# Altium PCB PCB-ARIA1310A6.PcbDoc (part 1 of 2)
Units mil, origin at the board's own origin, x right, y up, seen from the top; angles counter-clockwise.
Board outline 6000 x 4000 mil, 2 copper layers (Top Layer, Bottom Layer); 128 components, 134 nets, 554 pads, 227 vias.
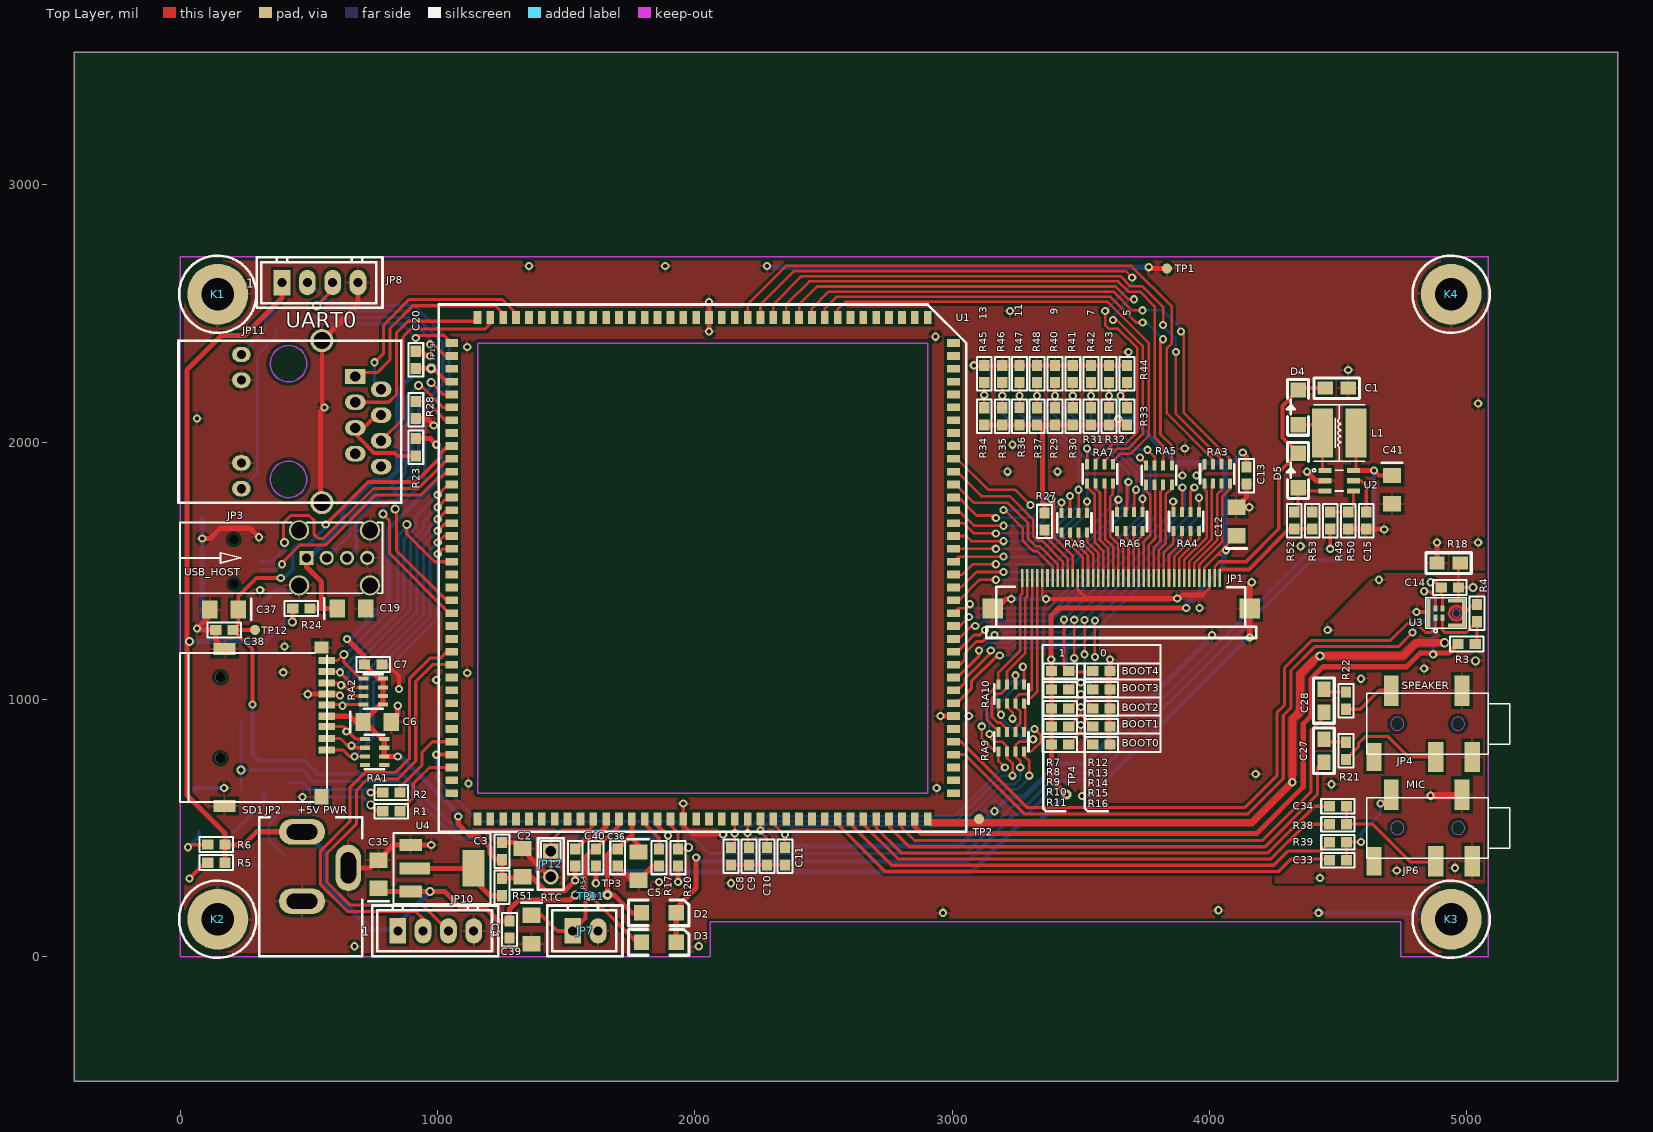
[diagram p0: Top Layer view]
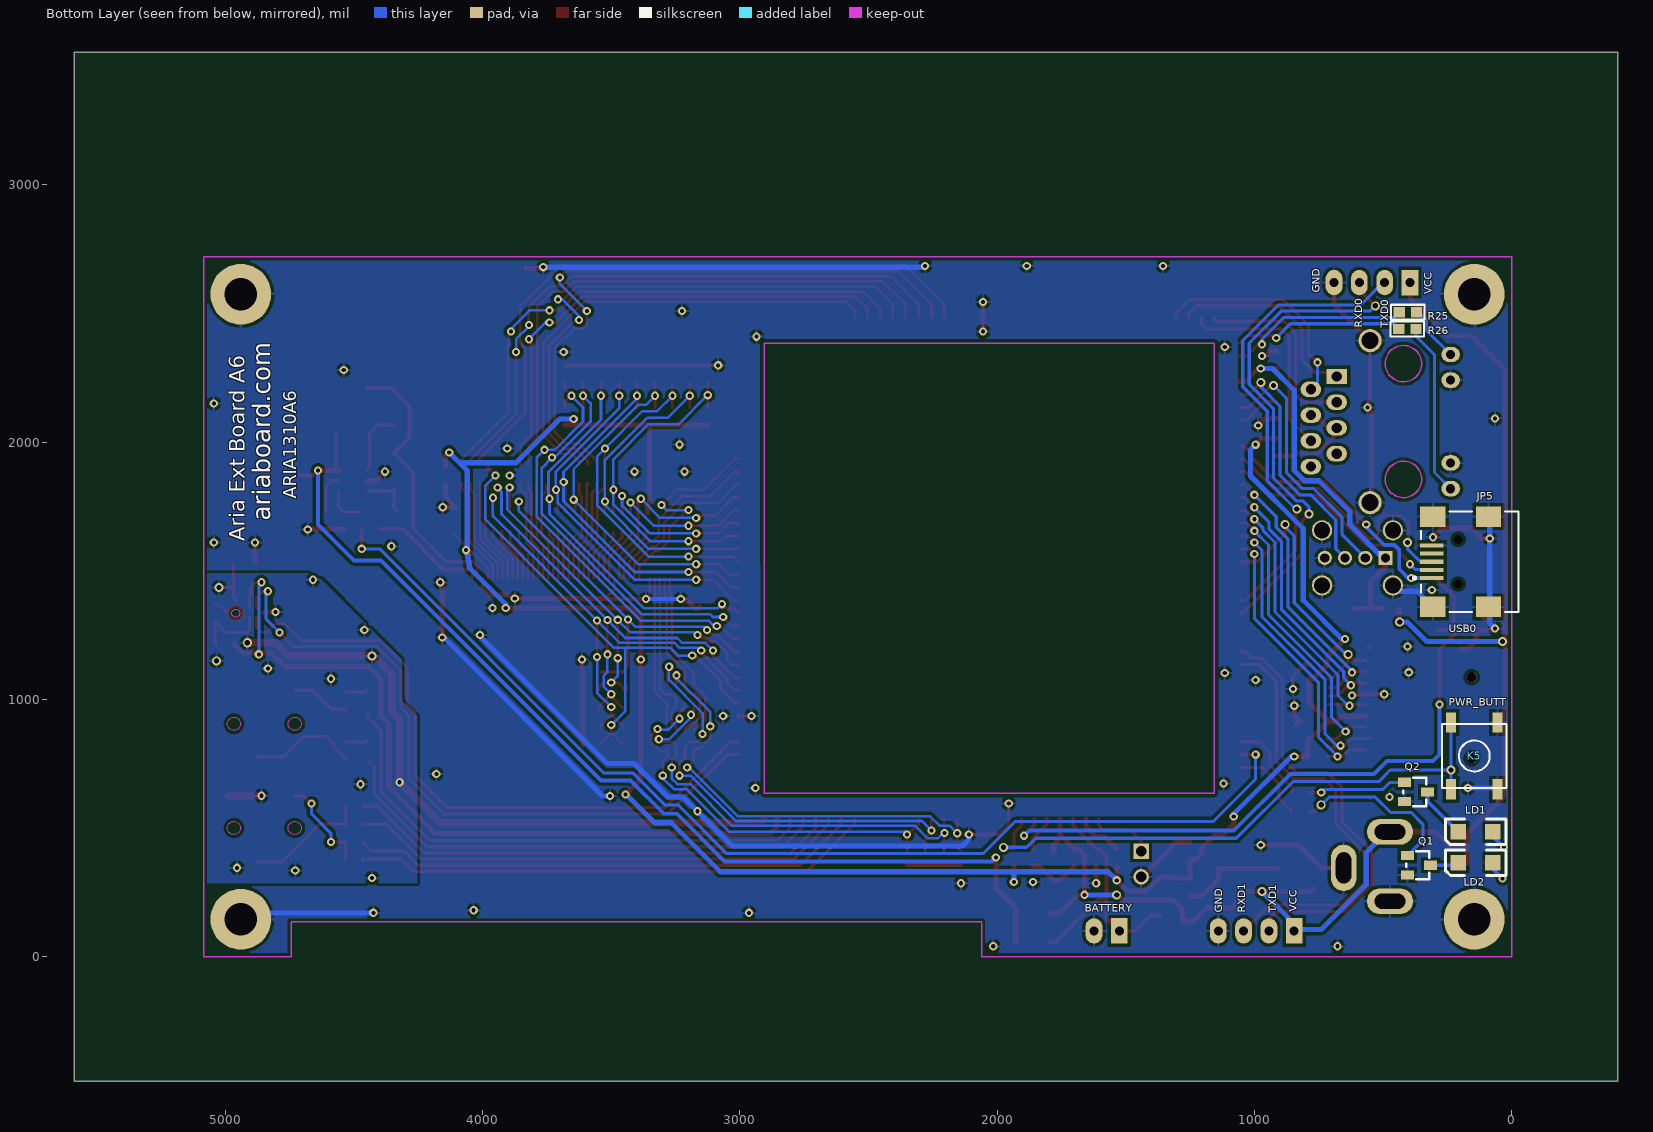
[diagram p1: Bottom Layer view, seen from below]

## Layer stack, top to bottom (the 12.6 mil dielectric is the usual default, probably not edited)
Top Layer: signal copper 1.4
Dielectric: dielectric 12.6, FR-4, Dk 4.8
Bottom Layer: signal copper 1.4

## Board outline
-412.52,-484.61 5587.48,-484.61 5587.48,3515.39 -412.52,3515.39

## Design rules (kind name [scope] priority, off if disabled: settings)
Clearance Clearance_2 [All] p1 off: gap=12
Clearance Clearance_1 [All] p2: gap=8
ComponentClearance [All] p1: gap=0 collisioncheckmode=3 verticalgap=0 showdistances=FALSE
HoleSize [All] p1: absolutevalues=TRUE maxlimit=1000 minlimit=10 maxpercent=80.000 minpercent=20.000
PolygonConnect [All] p1: connectstyle=Relief reliefconductorwidth=10 reliefentries=4 polygonreliefangle="90 Angle"
RoutingVias [All] p1: holewidth=18 width=36 viastyle="Through Hole" minholewidth=12 minwidth=24 maxholewidth=1000 maxwidth=3000
SolderMaskExpansion [All] p1: expansion=4
TestPointUsage FabricationTestPointUsage [All] p1: valid=0 allowmultiple=FALSE
Testpoint FabricationTestpoint [All] p1: side=3 testpointundercomponent=TRUE minsize=40 maxsize=100 preferedsize=60 minholesize=0 maxholesize=40 preferedholesize=32 testpointgrid=1 style=297 order=0123456789
Width Width_2 [InNet('VCC')] p1: maxlimit=50 minlimit=20 preferedwidth=30
Width Width_1 [All] p2: maxlimit=50 minlimit=10 preferedwidth=10
Width [All] p3 off: maxlimit=15 minlimit=12 preferedwidth=12
17 further rules are at their usual default settings.

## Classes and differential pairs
component class LCD: C1 C2 C3 C12 C13 C15 C41 D2 D3 D4 D5 JP1 L1 R27 R49 R50 R52 R53 RA3 RA4 RA5 RA6 RA7 RA8 RA9 RA10 U2
component class Audio&Net: C14 C27 C28 C33 C34 JP4 JP6 JP11 K1 K2 K3 K4 R3 R4 R18 R21 R22 R23 R25 R26 R38 R39 U3
component class Connect: C19 C20 C35 C36 C37 C38 C39 C40 JP2 JP3 JP5 JP7 JP8 JP10 R24 R28 R51 TP1 TP3 TP4 TP11 TP12 TP13 U4
net class LCD_DATA[23..0]: LCD_DATA0 LCD_DATA1 LCD_DATA2 LCD_DATA3 LCD_DATA4 LCD_DATA5 LCD_DATA6 LCD_DATA7 LCD_DATA8 LCD_DATA9 LCD_DATA10 LCD_DATA11 LCD_DATA12 LCD_DATA13 LCD_DATA14 LCD_DATA15 LCD_DATA16 LCD_DATA17 LCD_DATA18 LCD_DATA19 LCD_DATA20 LCD_DATA21 LCD_DATA22 LCD_DATA23
component class Core: C4 C5 C6 C7 C8 C9 C10 C11 JP12 K5 LD1 LD2 Q1 Q2 R1 R2 R5 R6 R7 R8 R9 R10 R11 R12 R13 R14 R15 R16 R17 R20 R29 R30 R31 R32 R33 R34 R35 R36 R37 R40 R41 R42 R43 R44 R45 R46 R47 R48 R54 RA1 RA2 SD1 TP2 U1

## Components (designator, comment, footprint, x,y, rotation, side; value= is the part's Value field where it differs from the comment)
C1 "1uF" U2012-0805 4495,2210 r0 top
C2 "10uF" CC3216-1206#1 1330,365 r90 top
C3 "100nF" U1608-0603 1250,410 r270 top
C4 "100nF" U1608-0603 1280,105 r90 top
C5 "10uF" CC3216-1206#1 1780,351.54 r270 top
C6 "10uF" CC3216-1206#1 765,911.97 r0 top
C7 "100nF" U1608-0603 749.65,1135 r0 top
C8 "1nF" U1608-0603 2140,390 r270 top
C9 "1nF" U1608-0603 2210,390 r270 top
C10 "1nF" U1608-0603 2280,390 r270 top
C11 "1nF" U1608-0603 2350,390 r270 top
C12 "10uF" CC3216-1206#1 4105,1691.5 r90 top
C13 "100nF" U1608-0603 4145,1870 r90 top
C14 "100nF" U1608-0603 4935,1435 r180 top
C15 "33nF" U1608-0603 4610,1695 r90 top
C19 "10uF" CC3216-1206#1 665,1352.72 r0 top
C20 "100nF" U1608-0603 915,2320 r270 top
C27 "47uF" U2012-0805 4445.62,799.97 r270 top
C28 "47uF" U2012-0805 4445.62,994.97 r270 top
C33 "100nF" U1608-0603 4500,374.38 r180 top
C34 "100nF" U1608-0603 4499.97,584.38 r180 top
C35 "10uF" CC3216-1206#1 770,320 r90 top
C36 "100nF" U1608-0603 1700,385 r90 top
C37 "10uF" CC3216-1206#1 170,1350 r180 top
C38 "100nF" U1608-0603 171.04,1270 r0 top
C39 "10uF" CC3216-1206#1 1365,105 r270 top
C40 "100nF" U1608-0603 1615,385 r90 top
C41 "10uF" CC3216-1206#2 4710,1815 r90 top
D2 "1N4148" LED1206 1860,170 r0 top
D3 "1N4148" LED1206 1860,55 r0 top
D4 "MSS1P3L" DI1206 4345,2135 r90 top
D5 "BZV55-B20" DI1206 4345,1890 r90 top
JP1 "HEADER 40" FFC0.5-40TOP 4040,1471.5 r0 top locked
JP2 "PWR2.5" POWER 652.64,345 r270 top locked
JP3 "USB" USB-A_1 490,1550 r0 top locked
JP4 "AUD2.5" PJ327A 5085,905 r180 top
JP5 "USB" USB_SM 200,1535 r180 bottom locked
JP6 "AUD2.5" PJ327A 5085,500 r180 top
JP7 "HEADER 2" CON-25/02/TC 1525,100 r0 top locked
JP8 "HEADER 4" CON-25/04/TC 395,2620 r0 top
JP10 "HEADER 4" CON-25/04/TC 845,100 r0 top
JP11 "RJ45_HR911105A" RJ45_HR911105A 680,2255 r180 top locked
JP12 "RTC" SIP\2P 1440,410 r270 top
K1 "HOLE" SS-TOTAL-32 145,2575 r0 top locked
K2 "HOLE" SS-TOTAL-32 145,145 r0 top locked
K3 "HOLE" SS-TOTAL-32 4940,145 r0 top locked
K4 "HOLE" SS-TOTAL-32 4940,2575 r0 top locked
K5 "KEY_PUSH4" KEY6.5X6.5B 145,780 r180 bottom
L1 "10uH/100mA" L5*5 4505,2035 r90 top
LD1 "LED" LED1206 140,365 r0 bottom
LD2 "LED" LED1206 140,485 r0 bottom
Q1 "S8050" SOT23 360,355 r270 bottom
Q2 "S8050" SOT23 371.54,640 r270 bottom
R1 "10K" U1608-0603 820.12,565 r180 top
R2 "10K" U1608-0603 820.12,637.5 r180 top
R3 "10K/DNI" U1608-0603 5000,1215 r180 top
R4 "10K" U1608-0603 5040,1335 r270 top
R5 "1K" U1608-0603 140,365 r180 top
R6 "1K" U1608-0603 140,435 r180 top
R7 "100K" U1608-0603 3420,1110 r0 top
R8 "100K" U1608-0603 3420,1037.6 r0 top
R9 "100K" U1608-0603 3420,965 r0 top
R10 "100K" U1608-0603 3420,895 r0 top
R11 "100K" U1608-0603 3420,825 r0 top
R12 "100K" U1608-0603 3580,1110 r0 top
R13 "100K" U1608-0603 3580,1037.6 r0 top
R14 "100K" U1608-0603 3580,965 r0 top
R15 "100K" U1608-0603 3580,895 r0 top
R16 "100K" U1608-0603 3580,825 r0 top
R17 "4.7K" U1608-0603 1860,385 r90 top
R18 "0 / DNI" U2012-0805 4930,1530 r180 top
R20 "10K" U1608-0603 1935,385 r90 top
R21 "33" U1608-0603 4530.62,799.97 r90 top
R22 "33" U1608-0603 4530.62,994.97 r90 top
R23 "0" U1608-0603 915,1980 r270 top
R24 "0" U1608-0603 470,1352.72 r0 top
R25 "2K" U1608-0603 403.46,2505 r0 bottom
R26 "2K" U1608-0603 405,2440 r0 bottom
R27 "10K" U1608-0603 3358.46,1691.5 r90 top
R28 "0" U1608-0603 915,2125 r270 top
R29 "100K" U1608-0603 3400,2100 r90 top
R30 "100K" U1608-0603 3469.13,2100 r90 top
R31 "100K" U1608-0603 3540,2100 r90 top
R32 "100K" U1608-0603 3610,2100 r90 top
R33 "100K" U1608-0603 3680,2100 r90 top
R34 "100K" U1608-0603 3125,2100 r90 top
R35 "100K" U1608-0603 3195,2100 r90 top
R36 "100K" U1608-0603 3262.48,2100.39 r90 top
R37 "100K" U1608-0603 3330,2100 r90 top
R38 "2K" U1608-0603 4499.97,514.38 r0 top
R39 "2K" U1608-0603 4500,444.38 r0 top
R40 "100K" U1608-0603 3400,2265 r90 top
R41 "100K" U1608-0603 3469.13,2265 r90 top
R42 "100K" U1608-0603 3540,2265 r90 top
R43 "100K" U1608-0603 3610,2265 r90 top
R44 "100K" U1608-0603 3680,2265 r90 top
R45 "100K" U1608-0603 3125,2265 r90 top
R46 "100K" U1608-0603 3195,2265 r90 top
R47 "100K" U1608-0603 3262.48,2265 r90 top
R48 "100K" U1608-0603 3330,2265 r90 top
R49 "1K" U1608-0603 4470,1695 r90 top
R50 "100K" U1608-0603 4540,1695 r90 top
R51 "0" U1608-0603 1250,270 r90 top
R52 "1K" U1608-0603 4330,1695 r270 top
R53 "62" U1608-0603 4400,1695 r270 top
R54 "0 / DNI" U1608-0603 1535,385 r90 top
RA1 "10K" RP4 755,795 r0 top
RA2 "10K" RP4 749.65,1030 r0 top
RA3 "33" RP4 4030.67,1876.5 r90 top locked
RA4 "33" RP4 3910,1691.5 r90 top locked
RA5 "33" RP4 3803.78,1871.5 r90 top locked
RA6 "33" RP4 3690.67,1691.5 r90 top locked
RA7 "33" RP4 3575,1876.5 r90 top locked
RA8 "33" RP4 3475,1686.5 r90 top locked
RA9 "0 / DNI" RP4 3230,835 r90 top
RA10 "0" RP4 3230,1020.98 r270 top
SD1 "SD_SKT,FS009-2002" DWM-1007A 568.74,895 r270 top locked
TP1 "PAD" TP10C 3835,2675 r90 top
TP2 "PAD" TP10C 3105,535 r180 top
TP3 "PAD" TP10C 1660,240 r90 top
TP4 "PAD" TP10C 3445,630 r90 top
TP11 "PAD" TP10C 1595,235 r90 top
TP12 "PAD" TP10C 290,1270 r90 top
TP13 "PAD" TP10C 975,2286.54 r90 top
U1 "AM335X144-A5" AM335X_144_50B 2030,1510 r180 top locked
U2 "AIC1896PG" SOT_26 4505,1850 r270 top
U3 "ADMP521" ? 4960,1335 r0 top
U4 "LM1117-3V3" SOT223 895,433.58 r270 top locked

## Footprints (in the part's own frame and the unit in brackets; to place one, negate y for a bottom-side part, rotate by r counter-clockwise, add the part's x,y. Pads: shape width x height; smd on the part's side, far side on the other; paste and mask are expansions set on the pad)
AM335X_144_50B [mil]
  rect 30x50 smd: 1(-875,-975) 2(-825,-975) 3(-775,-975) 4(-725,-975) 5(-675,-975) 6(-625,-975) 7(-575,-975) 8(-525,-975) 9(-475,-975) 10(-425,-975) 11(-375,-975) 12(-325,-975) 13(-275,-975) 14(-225,-975) 15(-175,-975) 16(-125,-975) 17(-75,-975) 18(-25,-975) 19(25,-975) 20(75,-975) 21(125,-975) 22(175,-975) 23(225,-975) 24(275,-975) 25(325,-975) 26(375,-975) 27(425,-975) 28(475,-975) 29(525,-975) 30(575,-975) 31(625,-975) 32(675,-975) 33(725,-975) 34(775,-975) 35(825,-975) 36(875,-975) 73(875,975) 74(825,975) 75(775,975) 76(725,975) 77(675,975) 78(625,975) 79(575,975) 80(525,975) 81(475,975) 82(425,975) 83(375,975) 84(325,975) 85(275,975) 86(225,975) 87(175,975) 88(125,975) 89(75,975) 90(25,975) 91(-25,975) 92(-75,975) 93(-125,975) 94(-175,975) 95(-225,975) 96(-275,975) 97(-325,975) 98(-375,975) 99(-425,975) 100(-475,975) 101(-525,975) 102(-575,975) 103(-625,975) 104(-675,975) 105(-725,975) 106(-775,975) 107(-825,975) 108(-875,975)
  rect 50x30 smd: 37(975,-875) 38(975,-825) 39(975,-775) 40(975,-725) 41(975,-675) 42(975,-625) 43(975,-575) 44(975,-525) 45(975,-475) 46(975,-425) 47(975,-375) 48(975,-325) 49(975,-275) 50(975,-225) 51(975,-175) 52(975,-125) 53(975,-75) 54(975,-25) 55(975,25) 56(975,75) 57(975,125) 58(975,175) 59(975,225) 60(975,275) 61(975,325) 62(975,375) 63(975,425) 64(975,475) 65(975,525) 66(975,575) 67(975,625) 68(975,675) 69(975,725) 70(975,775) 71(975,825) 72(975,875) 109(-975,875) 110(-975,825) 111(-975,775) 112(-975,725) 113(-975,675) 114(-975,625) 115(-975,575) 116(-975,525) 117(-975,475) 118(-975,425) 119(-975,375) 120(-975,325) 121(-975,275) 122(-975,225) 123(-975,175) 124(-975,125) 125(-975,75) 126(-975,25) 127(-975,-25) 128(-975,-75) 129(-975,-125) 130(-975,-175) 131(-975,-225) 132(-975,-275) 133(-975,-325) 134(-975,-375) 135(-975,-425) 136(-975,-475) 137(-975,-525) 138(-975,-575) 139(-975,-625) 140(-975,-675) 141(-975,-725) 142(-975,-775) 143(-975,-825) 144(-975,-875)
  Keep-Out Layer lines w5: 875,875 -875,875 -875,-875 875,-875 875,875
  silkscreen extent -1025,-1025 1025,1025
CC3216-1206#1 [mil]
  rect 60x70 smd: 1(-55.12,0) 2(55.12,0)
  silkscreen extent -105,-40 -105,40
CC3216-1206#2 [mil]
  rect 60x70 smd: 1(55.12,0) 2(-55.12,0)
  silkscreen extent 105,-40 105,40
CON-25/02/TC [mil]
  rect 65x98.42 hole 35: 1(0,0)
  oval 65x98.42 hole 35: 2(98.43,0)
  silkscreen extent -98,-98 194,98
CON-25/04/TC [mil]
  rect 65x98.42 hole 35: 1(0,0)
  oval 65x98.42 hole 35: 2(98.42,0) 3(196.85,0) 4(295.28,0)
  silkscreen extent -98,-98 391,98
DI1206 [mil]
  rect 60x60 smd: 1(-67.5,0) 2(67.5,0)
  silkscreen extent -108,-41 108,43
DWM-1007A [mm]
  rect 0.7x1.6 smd: 1(2.35,0) 2(1.2,0) 3(0,0) 4(-1,0) 5(-2.1,0) 6(-3.2,0) 7(-4.3,0) 8(-5.4,0) 9(-6.5,0)
  rect 1.2x1.4 smd: 10(-7.772,-0.508)
  rect 1.5x1.4 smd: 11(6.95,-0.5)
  rect 1.2x2.2 smd: A(-7.651,-10.102) A(7.849,-10.102)
  round 1 hole 1 unplated: B(-4.85,-10.5)
  round 1 hole 1: B(3.15,-10.5)
  silkscreen extent -7.25,-14.48 7.45,0.03
FFC0.5-40TOP [mm]
  rect 0.254x1.8 smd: 1(0,0) 2(-0.5,0) 3(-1,0) 4(-1.5,0) 5(-2,0) 6(-2.5,0) 7(-3,0) 8(-3.5,0) 9(-4,0) 10(-4.5,0) 11(-5,0) 12(-5.5,0) 13(-6,0) 14(-6.5,0) 15(-7,0) 16(-7.5,0) 17(-8,0) 18(-8.5,0) 19(-9,0) 20(-9.5,0) 21(-10,0) 22(-10.5,0) 23(-11,0) 24(-11.5,0) 25(-12,0) 26(-12.5,0) 27(-13,0) 28(-13.5,0) 29(-14,0) 30(-14.5,0) 31(-15,0) 32(-15.5,0) 33(-16,0) 34(-16.5,0) 35(-17,0) 36(-17.5,0) 37(-18,0) 38(-18.5,0) 39(-19,0) 40(-19.5,0)
  rect 2x2 smd: 41(-22.4,-3) 41(2.972,-2.997)
  silkscreen extent -23.05,-5.92 3.63,-0.86
KEY6.5X6.5B [mil]
  rect 39.37x78.74 smd: 1(-90,130) 2(-90,-130) 3(90,-130) 4(90,130)
  silkscreen extent -125,-125 125,125
L5*5 [mil]
  rect 190x80 smd: 1(0,65) 2(0,-65)
  silkscreen extent -110,-100 110,100
LED1206 [mil]
  rect 60x60 smd: 1(-67.5,0) 2(67.5,0)
  silkscreen extent -118,-50 118,50
PJ327A [mm]
  rect 1.5x2.8 smd: 1(11.3,3.28)
  rect 1.5x3 smd: 2(5.2,3.28) 3(1.6,3.28) 4(2.6,-3.28)
  rect 1.4x3 smd: 5(9.6,-3.28)
  Keep-Out Layer circle w0.1: c9,0 r0.65
  Keep-Out Layer circle w0.1: c3,0 r0.65
  silkscreen extent -2.1,-3 12,3
POWER [mil]
  oval 100x180 hole 60 slot 120 at 90 deg: 1(-140,-180) 2(130,-180)
  oval 180x100 hole 60 slot 120 at 0 deg: 3(0,0)
  silkscreen extent -196,-346 344,54
RJ45_HR911105A [mil]
  rect 80x60 hole 40: 1(0,0)
  oval 80x60 hole 40: 2(-100,50) 3(0,100) 4(-100,150) 5(0,200) 6(-100,250) 7(0,300) 8(-100,350)
  oval 72x60 hole 36: 9(442.91,-85.63) 10(442.91,14) 11(442.91,335.87) 12(442.91,436)
  round 90 hole 65: 13(129.92,490.16) 13(129.92,-139.76)
  Keep-Out Layer circle w5: c260,-50 r70.8
  Keep-Out Layer circle w5: c260,400 r70.8
  silkscreen extent -179,-140 687,490
RP4 [mm]
  rect 1x0.4 smd: 1(-0.95,-1.275) 2(-0.95,-0.425) 3(-0.95,0.425) 4(-0.95,1.275) 5(0.95,1.275) 6(0.95,0.425) 7(0.95,-0.425) 8(0.95,-1.275)
  silkscreen extent -0.95,-1.7 0.95,1.7
SIP\2P [mil]
  rect 60x60 / inner round 60 / far side rect 60x60 hole 40: 1(0,0)
  round 60 hole 40: 2(100,0)
  silkscreen extent -50,-50 150,50
SOT23 [mil]
  rect 36x50 smd: 1(-37.5,-45) 2(37.5,-45) 3(0,45)
  silkscreen extent -55,-50 55,40
SOT223 [mm]
  rect 1.2x2.2 smd: 1(0,0) 3(4.6,0)
  rect 1.2x3.048 smd: 2(2.3,0.406)
  rect 3.6x2.2 smd: 4(2.3,6.2)
  silkscreen extent -1.2,-1.7 5.8,7.9
SOT_26 [mil]
  rect 20x50 smd: 1(-40,-55) 2(0,-55) 3(40,-55) 4(40,55) 5(0,55) 6(-40,55)
  silkscreen extent -47,-104 40,15
SS-TOTAL-32 [mm]
  round 6 hole 3.2: 1(0,0)
  silkscreen extent -3.81,-3.81 3.81,3.81
TP10C [mm]
  round 1 smd: 1(0,0)
U1608-0603 [mm]
  rect 1.1x1 smd: 1(-0.85,0) 2(0.85,0)
  silkscreen extent -1.65,-0.74 1.65,0.74
U2012-0805 [mil]
  rect 60x50 smd: 1(-45,0) 2(45,0)
  silkscreen extent -88,-40 88,40
USB-A_1 [mm]
  rect 1.4x1.4 hole 0.9: 1(0,0)
  round 1.4 hole 0.9: 2(2,0) 3(4,0) 4(6,0)
  round 2 hole 1.6: 5(-0.73,2.72) 6(-0.73,-2.72) 7(6.27,2.72) 8(6.27,-2.72)
  silkscreen extent -12.48,-3.5 7.52,3.5
USB_SM [mm] "Connector; USB2.0, Type B, SM; 5 Position; Right Angle"
  rect 2.3x0.406 smd: 1(-2.8,-1.6) 2(-2.8,-0.8) 3(-2.8,0) 4(-2.8,0.8) 5(-2.8,1.6)
  rect 2.5x2 smd: 6(-2.7,4.45) 7(2.8,4.45) 8(-2.7,-4.45) 9(2.8,-4.45)
  round 0.6 hole 0.9 unplated: MH1(-0.2,2.2) MH2(-0.2,-2.2)
  silkscreen extent -4.63,-4.95 5.75,4.95
? [mm]
  rect 0.4x0.6 smd: 1(-2.05,-0.45) 2(-1.35,-0.45) 4(-1.35,0.45) 5(-2.05,0.45)
  rect 0.35x2.8 smd: 3(-2.718,0) 3(0.725,0)
  rect 1.4x0.35 smd: 3(-0.127,-1.219) 3(-0.127,1.219)
  Top Layer circle w0.3: c0,0 r0.7
  Keep-Out Layer circle w0.051: c0,0 r0.4
  silkscreen extent -3,-1.93 1,1.5

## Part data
C1: library part CAP_01
C2 C5 C6 C12 C19 C35 C37 C39 C41: library part "Cap Pol2", "Polarized Capacitor (Axial)"
C3 C4 C7 C8 C9 C10 C11 C13 C14 C15 C20 C27 C28 C33 C34 C36 C38 C40: library part CAP_SIMO, "Capacitor"
D2 D3: "Diode"
D4: library part DIODE, "Default Diode"
D5: library part DIO-SOD80ZENER
JP1: "Header, 40-Pin"
JP2: "Low Voltage Power Supply Connector"
JP3: library part USB_HOST, "USB 1.1, Right Angle, Thru-Hole, A Type, Receptacle, 4 Position, Black"
JP4 JP6: "Header 5"
JP5: library part USB_SM, "USB 2.0, Right Angle, SMT, B Type, Receptacle, 5 Position, Black"
JP7: "Header 2 2 Pin"
JP8 JP10: "Header, 4-Pin"
JP12: library part "HEADER 2", "Header 2 2 Pin"
L1: library part INDUCTOR
LD1 LD2: "Typical RED, GREEN, YELLOW, AMBER GaAs LED"
Q1 Q2: library part S8050LT1(NPN), "NPN Bipolar Transistor"
R1 R2 R3 R4 R5 R6 R7 R8 R9 R10 R11 R12 R13 R14 R15 R16 R17 R18 R20 R21 R22 R23 R24 R25 R26 R27 R28 R29 R30 R31 R32 R33 R34 R35 R36 R37 R38 R39 R40 R41 R42 R43 R44 R45 R46 R47 R48 R49 R50 R51 R52 R53 R54: library part RES1, "Resistor"
RA1 RA2 RA3 RA4 RA5 RA6 RA7 RA8 RA9 RA10: library part RP4R
SD1: library part SD_SKT_1
TP1 TP2 TP3 TP4 TP11 TP12 TP13: library part "TEST POINT_0"
U2: library part AIC1896
U4: library part LM1117, "800mA and 1A Low Dropout Positive Regulator 2.85V, 3.3V, 5V, and Adjustable"

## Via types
v1: diameter 32, hole 16, Top Layer to Bottom Layer, 208 vias
v2: diameter 35, hole 20, Top Layer to Bottom Layer, 19 vias

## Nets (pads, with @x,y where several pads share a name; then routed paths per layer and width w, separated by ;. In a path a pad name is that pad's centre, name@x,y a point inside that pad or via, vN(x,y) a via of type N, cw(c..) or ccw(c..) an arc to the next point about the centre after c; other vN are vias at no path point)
AU_DM_CLOCK: U1.113 U3.1 | length 2565.2
  Top Layer w12: U1.113@3005,835 3035,835 3290,580 4139.64,580 4262.22,702.57 4262.22,947.57 4292.22,977.57 4292.22,1122.57 4399.04,1229.39 4704.39,1229.39 4770,1295 4805,1295 4840,1260 4860.28,1260 4879.29,1279.02 U3.1@4879.29,1317.28
AU_DM_DATA: U1.112 U3.5 | length 2682.4
  Top Layer w12: U1.112@3005,785 3050,785 3280,555 4150,555 4287.22,692.22 4287.22,937.22 4317.22,967.22 4317.22,1112.22 4410,1205 4735,1205 v1(4790,1260) ; v1(4835,1420) 4855,1420 4879.29,1395.71 U3.5@4879.29,1352.72
  Bottom Layer w12: v1(4790,1260) 4841.89,1311.89 4841.89,1413.11 v1(4835,1420)
AUGND: C14.1 JP4.3 JP4.4 JP6.3 JP6.4 R4.1 R18.1 TP2.1 U1.108 U3.3 | length 2988.8
  Top Layer w11.81: U3.3@4955,1383.01 4968.46,1396.48 C14.1@4968.46,1435 ; R18.1@4975,1530 4968.46,1523.46 C14.1@4968.46,1435 ; U3.3@4991.25,1335 5024.72,1368.46 R4.1@5040,1368.46 ; v2(5025,1435) C14.1@4968.46,1435
  Top Layer w15: v1(4805,1340) 4848,1340 U3.3@4853,1335
  Top Layer w30: U1.108@2905,535 2920,520 4165,520 v1(4322.57,677.57) 4322.57,922.57 4352.57,952.57 4352.57,1097.57 4424.04,1169.04 4754.04,1169.04 4805,1220 v2(4915,1220) ; v1(4860.11,625.21) JP6.4@4989.83,625.21
  other v1: 4430,305 4728.46,335 4955,345 4475,670 4590,1080.2 4835,1120 4460,1270 4660,1465
  other v2: 5035,1150 4430,1169.04
AUVDD: C14.2 R3.2 U1.107 U3.4 | length 3104.1
  Top Layer w12: v1(4860,1455) 4881.54,1455 C14.2@4901.54,1435 4901.54,1408.46 4906.85,1403.15 U3.4@4906.85,1352.72
  Top Layer w20: U1.107@2855,535 2855,505 2881,479 4184,479 4365,660 4365,905 4395,935 4395,1080 4441.61,1126.61 4766.61,1126.61 4820,1180 4931.54,1180 R3.2@4966.54,1215
  Bottom Layer w12: v1(4860,1455) 4870,1445 v1(4870,1175)
DGND: C1.2 C2.2 C3.1 C4.1 C5.2 C6.2 C7.2 C8.2 C9.2 C10.2 C11.2 C12.2 C13.1 C15.1 C19.2 C20.1 C35.2 C36.1 C37.2 C38.1 C39.2 C40.1 C41.2 JP1.3 JP1.29 JP1.36 JP1.41 JP2.2 JP2.3 JP3.4 JP3.5 JP3.6 JP3.7 JP3.8 JP5.5 JP5.6 JP5.7 JP5.8 JP5.9 JP7.2 JP8.4 JP10.4 JP11.10 JP11.11 JP11.13 JP12.2 K1.1 K2.1 K3.1 K4.1 K5.3 K5.4 Q1.2 Q2.2 R12.2 R13.2 R14.2 R15.2 R16.2 R17.1 R18.2 R28.2 R40.2 R41.2 R42.2 R43.2 R44.2 R45.2 R46.2 R47.2 R48.2 R50.1 R53.1 SD1.6 SD1.10 SD1.11 SD1.A TP1.1 U1.18 U1.89 U1.115 U2.2 U4.1 | length 12419.3
  Top Layer w10: JP1.36@3351.02,1471.5 3351.02,1400.47 3353,1398.5 3365,1398.5 v1@3356.5,1390 ; 3488.82,1426.18 JP1.29@3488.82,1471.5 ; 3973.5,1405 4000.63,1432.13 JP1.3@4000.63,1471.5
  Top Layer w12: 3488.82,1426.18 3525,1390
  Top Layer w15: K1.1@145,2575 K1.1@170,2550 ; SD1.10@548.74,1201 SD1.10@561,1201 ; SD1.11@549.05,613.45 SD1.11@549.05,621.38 ; JP11.13@550.08,2394.76 550.08,2144.92 v1(560,2135) ; JP2.3@652.64,345 JP2.3@665,357.36 ; C7.2@783.11,1135 805,1135 850,1090 v1(850,1040) ; C6.2@820.12,911.97 828.03,911.97 C6.2@840,900 ; v1(1955,594.97) U1.89@1955,535 1955,511.54 1991.54,475 v1(2110,475) ; C8.2@2140,356.54 C9.2@2210,356.54 C10.2@2280,356.54 C11.2@2350,356.54 ; v1@3080,2298.46 v1(3084.53,2298.46) R45.2@3125,2298.46 R46.2@3195,2298.46 R47.2@3262.48,2298.46 R48.2@3330,2298.46 R40.2@3400,2298.46 R41.2@3469.13,2298.46 R42.2@3540,2298.46 R43.2@3610,2298.46 R44.2@3680,2298.46 ; v1(3365,1390) 3525,1390
  Top Layer w20: v1(84.76,1625) 115,1625 155,1665 270.24,1665 v1(305.24,1630) ; C37.2@114.88,1350 114.88,1324.88 v1(65,1275) 70,1270 C38.1@137.58,1270 137.58,1229.68 SD1.A@171.04,1196.22 SD1.A@197.52,1196.22 ; v1(495,1020) 495.98,1020.98 SD1.6@568.74,1020.98 619.02,1020.98 v1@620,1020 ; JP11.13@545,1740.83 545,2120 v1(560,2135) ; JP11.13@550.08,2394.76 690.28,2534.96 JP8.4@690.28,2620 ; JP2.3@652.64,345 739.88,345 C35.2@770,375.12 828.46,433.58 U4.1@895,433.58 v1(975,433.58) ; C6.2@820.12,911.97 845,936.85 v1(845,975) ; R28.2@915,2091.54 958.46,2091.54 v1(985,2065) ; C20.1@915,2353.46 936.54,2353.46 955,2335 v1(970,2335) ; C3.1@1250,443.46 1306.65,443.46 C2.2@1330,420.12 1330,415 1435,310 JP12.2@1440,310 ; v1(1615,285) C40.1@1615,351.54 ; C36.1@1700,351.54 1755.12,296.42 C5.2@1780,296.42 1835.12,351.54 R17.1@1860,351.54 ; v1@2055,2430 U1.18@2055,2485 v1@2055,2545 ; v1(2955,935) U1.115@3005,935 ; JP1.41@3158.11,1359.61 JP1.41@3158.11,1353.39 3173.39,1353.39 3210,1390 v1(3230,1390) ; 3527.5,1392.5 v1(3875,1392.5) 3880,1392.5 3892.5,1405 3973.5,1405 ; R16.2@3610.04,825 3610.04,1106 3613.46,1109.43 R12.2@3613.46,1110 v1(3613.46,1155) ; v1(3764.41,2680) 3769.41,2675 TP1.1@3835,2675 ; C13.1@4145,1836.54 4145,1786.62 C12.2@4105,1746.62 v1(4155,1746.62) ; v1(4157,1240) JP1.41@4157,1353.5 4157,1447 v1(4165,1455) ; v1(4380,1885) 4415,1850 U2.2@4450,1850 ; R50.1@4540,1661.54 C15.1@4610,1661.54 4678.46,1661.54 v1(4680,1660) ; R18.2@4885,1530 v1(4885,1610)
  Bottom Layer w12: JP2.3@652.64,345 JP2.3@682.64,315
  Bottom Layer w15: v1(3230,1390) 3356.5,1390 v1@3365,1381.5
  Bottom Layer w20: K5.3@55,650 60,655 v1(170,655) ; v1(65,1275) 84.76,1294.76 v1(84.76,1625) JP5.7@84.76,1705.2 ; JP5.8@301.3,1354.8 JP5.8@306.3,1359.8 366.5,1420 438.35,1420 JP3.6@461.26,1442.91 ; JP2.3@620.14,312.5 JP2.3@652.64,345 ; JP3.4@726.22,1550 JP3.4@736.85,1560.63 ; v1(2110,475) 2110,455 2135,430 3030,430 v1(3165,565) 3220,620 3280,620 3410,750 3515,750 4015,1250 v1@4020.31,1250 ; v1@2280,2685 2285,2680 v1(3764.41,2680) ; v1(3505,624.38) 3534.38,624.38 v1@4153.5,1243.5 ; v1(4425,170) 4840,170 4865,145 K3.1@4940,145
  other v1: 676.73,40 2015,40 2965,170 4035,180 2140,285 1860,290 475,620 2940,655 1120,672.64 4180,710 3065,935 620,1015 995,1075 1115,1102.6 400,1105 405,1205 4010,1250 3961.26,1355 310,1425 4355,1595 5045,1610 3895,1870 3215,1885 3410,1885 3904.53,1975 3235,1990 65,2091.54 5045,2150 4540,2280 3685,2350 1115,2370 2935,2410 2054.88,2430.12 3225,2510 2054.88,2545.12 1355,2685 1885,2685 2279.88,2685.12
EGRNC: R25.2 U1.38 | length 702.3
  Top Layer w12: v1@970,2385 980,2385 1030,2335 U1.38@1055,2335
  Bottom Layer w12: R25.2@436.93,2505 456.93,2485 885,2485 970,2400 v1(970,2380)
ERX+: JP11.3 U1.36 | length 758.1
  Top Layer w12: JP11.3@680,2155 810,2155 840,2185 840,2425 885,2470 1150,2470 1155,2475 U1.36@1155,2485
ERX-: JP11.6 U1.35 | length 825.9
  Top Layer w12: JP11.6@780,2005 865,2090 865,2410 895,2440 1185,2440 1205,2460 U1.35@1205,2485
ETX+: JP11.1 U1.34 | length 787.7
  Top Layer w12: JP11.1@680,2255 695,2270 765,2270 815,2320 815,2441.89 903.11,2530 1225,2530 1255,2500 U1.34@1255,2485
ETX-: JP11.2 U1.33 | length 869.1
  Top Layer w12: v1(755,2310) 790,2345 790,2455 890,2555 1250,2555 1305,2500 U1.33@1305,2485
  Bottom Layer w12: v1(755,2310) 755,2230 JP11.2@780,2205
EYELC: R26.2 U1.37 | length 664.2
  Top Layer w12: v1(915,2405) 925,2415 1025,2415 U1.37@1055,2385
  Bottom Layer w12: R26.2@438.46,2440 458.46,2460 860,2460 v1(915,2405)
HPLOUT: C27.2 U1.105 | length 1950.3
  Top Layer w12: U1.105@2755,535 2755,505 2833,427 4217,427 4420,630 4420,734.97 4440,754.97 C27.2@4445.62,754.97
HPROUT: C28.2 U1.106 | length 2053.9
  Top Layer w12: U1.106@2805,535 2805,500 2854,451 4205.02,451 4395.62,641.61 4395.62,879.97 4445.62,929.97 C28.2@4445.62,949.97
I2C1_SCL: U1.66
I2C1_SDA: U1.64
LCD_AC_BIAS_EN: JP1.34 U1.135 | length 842.5
  Top Layer w10: U1.135@3005,1935 3020,1935 3140.59,1814.41 3245.94,1814.41 v1(3305,1755.36) ; v1@3204.66,1740.34 3204.66,1735.34 3275,1665 3275,1615.79 3315.79,1575 3331.5,1575 3390.39,1516.1 JP1.34@3390.39,1471.5
  Bottom Layer w10: v1(3200,1735.67) 3285.32,1735.67 v1(3305,1755.36)
LCD_B0: JP1.21 RA7.1 | length 384.8
  Top Layer w10: RA7.1@3625.2,1839.1 3625.2,1798.58 3615,1788.39 3615,1633.11 3646.3,1601.81 JP1.21@3646.3,1471.5
LCD_B1: JP1.22 RA7.2 | length 382
  Top Layer w10: RA7.2@3591.73,1839.1 3595,1835.83 3595,1624.2 3626.61,1592.58 JP1.22@3626.61,1471.5
LCD_B2: JP1.23 RA7.3 | length 387.8
  Top Layer w10: RA7.3@3558.27,1839.1 3558.27,1819.29 3575,1802.56 3575,1618.74 3606.93,1586.81 JP1.23@3606.93,1471.5
LCD_B3: JP1.24 RA7.4 | length 393.5
  Top Layer w10: RA7.4@3524.8,1839.1 3524.8,1825.2 3555,1795 3555,1609.06 3587.24,1576.81 JP1.24@3587.24,1471.5
LCD_B4: JP1.25 RA8.1 | length 195.1
  Top Layer w10: RA8.1@3525.2,1649.1 3525.2,1612.67 3567.56,1570.31 JP1.25@3567.56,1471.5
LCD_B5: JP1.26 RA8.2 | length 200.9
  Top Layer w10: RA8.2@3491.73,1649.1 3491.73,1620.68 3547.87,1564.54 JP1.26@3547.87,1471.5
LCD_B6: JP1.27 RA8.3 | length 206.6
  Top Layer w10: RA8.3@3458.27,1649.1 3458.27,1628.69 3528.19,1558.76 JP1.27@3528.19,1471.5
LCD_B7: JP1.28 RA8.4 | length 212.3
  Top Layer w10: RA8.4@3424.8,1649.1 3424.8,1635.2 3508.5,1551.5 JP1.28@3508.5,1471.5
LCD_BL: R49.1 U1.69 | length 4317.5
  Top Layer w12: v1(4470,1585) R49.1@4470,1661.54
  Top Layer w15: v1(995,785) U1.69@1055,785
  Bottom Layer w12: v1(995,785) 995,690 1160,525 1930,525 2055,400 3050.62,400 3240.62,590 3291.97,590 3415,713.03 3528.03,713.03 4400,1585 v1(4470,1585)
LCD_DATA0: R11.2 R16.1 RA3.5 U1.116 | length 2023.8
  Top Layer w10: R11.2@3453.46,825 3500,871.54 ; v1(3500,900) 3500,871.54 ; R16.1@3546.54,825 3500,871.54 ; v1(3950,1870) 3980.47,1900.47 RA3.5@3980.47,1913.9 RA3.5@3980.94,1914.37
  Top Layer w12: U1.116@3005,985 3018.27,985 3075,1041.73 3075,1070 3175,1170 v1(3185,1170)
  Bottom Layer w10: v1(3185,1170) 3240,1170 3270,1200 3445,1200 ; v1(3500,900) 3445,955 3445,1200 ; v1(3950,1870) 3990,1830 3990,1700.95 3489.05,1200 3445,1200
LCD_DATA1: R10.2 R15.1 RA4.8 U1.117 | length 1919.1
  Top Layer w10: R10.2@3450.28,881 R10.2@3450.28,890.28 ; R10.2@3453.46,895 3500,941.54 ; v1(3500,970) 3500,941.54 ; R15.1@3543.11,881 R15.1@3543.11,886.89 ; R15.1@3546.54,895 3500,941.54 ; v1(3555,1165) v1(3555,1306.96) ; v1(3960,1783.86) 3960.2,1783.66 RA4.8@3960.2,1728.9
  Top Layer w12: U1.117@3005,1035 3020,1035 3050,1065 3050,1080 3150,1180 v1(3150,1190)
  Bottom Layer w10: v1(3150,1190) 3161,1201 3236,1201 3255,1220 3468.04,1220 v1(3555,1306.96) 3960.2,1712.16 3960.2,1779.06 3965,1783.86 v1(3960,1783.86) ; v1(3500,970) 3555,1025 v1(3555,1165)
LCD_DATA2: R9.2 R14.1 RA4.7 U1.118 | length 1862.1
  Top Layer w10: R9.2@3453.46,965 3500,1011.54 v1(3500,1020) 3546.54,973.46 R14.1@3546.54,965 ; v1(3515,1175) v1(3515,1307.98) ; RA4.7@3926.73,1728.9 3926.73,1808.58 v1(3941.57,1823.43)
  Top Layer w12: U1.118@3005,1085 3020,1085 3105,1170 v1(3105,1190)
  Bottom Layer w10: v1(3105,1190) 3135,1220 3225,1220 3243.5,1238.5 3445.52,1238.5 v1(3515,1307.98) 3926.73,1719.71 3926.73,1805.16 3941.57,1820 v1(3941.57,1823.43) ; v1(3500,1020) 3530,1050 3530,1090.94 3515,1105.94 v1(3515,1175)
LCD_DATA3: R8.2 R13.1 RA4.6 U1.119 | length 1753.1
  Top Layer w10: R8.2@3453.46,1037.6 3453.46,1045.06 3473.4,1065 v1(3500,1065) 3531.6,1065 3546.54,1050.06 R13.1@3546.54,1037.6 ; v1(3475,1160) v1(3475,1308.99) ; RA4.6@3893.27,1728.9 3895,1730.63 v1(3895,1823.43)
  Top Layer w12: U1.119@3005,1135 3030,1135 3050,1155 3050,1180 3095,1225 3119.01,1225 3134.01,1240 3155,1240 v1(3165,1250) ; R8.2@3440,1051.49 3440,1039.22 R8.2@3447.31,1031.91
  Bottom Layer w10: v1(3165,1250) 3175,1260 3426.01,1260 v1(3475,1308.99) 3905,1738.99 3905,1813.43 v1(3895,1823.43) ; v1(3475,1160) 3475,1090 v1(3500,1065)
LCD_DATA4: R7.2 R12.1 RA4.5 U1.120 | length 1477.5
  Top Layer w10: v1(3435,1310) 3435,1128.46 R7.2@3453.46,1110 ; v1(3859.22,1769.22) 3859.22,1729.49 RA4.5@3859.8,1728.9
  Top Layer w12: U1.120@3021.91,1186.59 U1.120@3021.59,1186.59 ; v1(3127.52,1270) 3107.52,1250 3085,1250 U1.120@3021.59,1186.59 ; R7.2@3450.28,1106 R12.1@3543.11,1106 ; U1.120@3021.59,1186.59 3006.59,1186.59 U1.120@3005,1185 3020,1185 U1.120@3021.59,1186.59
  Bottom Layer w10: v1(3127.52,1270) 3139.02,1281.5 3406.5,1281.5 v1(3435,1310) 3860,1735 3860,1770 v1(3859.22,1769.22)
LCD_DATA5: R33.2 R44.1 RA5.6 U1.121 | length 1766.3
  Top Layer w10: U1.121@3010,1230 U1.121@3005,1235 3025,1235 3075,1285 v1(3090,1285) ; R33.2@3680,2133.46 3680,2157.98 3655.48,2182.5 3680,2207.02 R44.1@3680,2231.54 ; v1(3760,1970) 3787.05,1942.95 RA5.6@3787.05,1908.9
  Bottom Layer w10: v1(3090,1285) 3100,1285 3120,1305 3385,1305 3790,1710 3790,1940 v1(3760,1970) 3719.72,1970 3610,2079.72 3610,2135 v1(3655,2180)
LCD_DATA6: R32.2 R43.1 RA5.5 U1.122 | length 1641.1
  Top Layer w10: U1.122@3005,1285 3030,1285 v1(3065,1320) ; R32.2@3610,2133.46 v1(3610,2180) R43.1@3610,2231.54 ; v1(3730,1940) 3753.58,1916.42 RA5.5@3753.58,1908.9
  Bottom Layer w10: v1(3065,1320) 3105,1320 3115,1330 3380,1330 3770,1720 3770,1900 v1(3730,1940) 3720,1940 3580,2080 3580,2150 v1(3610,2180)
LCD_DATA7: R31.2 R42.1 RA6.8 U1.123 | length 1603.5
  Top Layer w10: U1.123@3005,1335 3023.39,1353.39 3053.39,1353.39 v1(3070,1370) ; R31.2@3540,2133.46 v1(3540,2180) R42.1@3540,2231.54 ; v1(3740,1780) 3740.87,1779.13 RA6.8@3740.87,1728.9
  Bottom Layer w10: v1(3070,1370) 3086.61,1353.39 3372.67,1353.39 3740,1720.72 v1(3740,1780) 3744,1784 3744,1884.46 3540,2088.46 v1(3540,2180)
LCD_DATA8: R30.2 R41.1 RA6.7 U1.124 | length 1568.6
  Top Layer w10: U1.124@3005,1385 3026.61,1385 3106.61,1465 v1(3170,1465) ; R30.2@3469.13,2133.46 v1(3469.13,2180) R41.1@3469.13,2231.54 ; RA6.7@3707.4,1728.9 3707.4,1807.4 v1(3715,1815)
  Bottom Layer w10: v1(3170,1465) 3410,1465 3707.4,1762.4 3707.4,1807.4 v1(3715,1815) 3715,1885 3469.13,2130.87 v1(3469.13,2180)
LCD_DATA9: R29.2 R40.1 RA6.6 U1.125 | length 1565.7
  Top Layer w10: U1.125@3005,1435 3035,1435 3095,1495 v1(3200,1495) ; R29.2@3400,2133.46 v1(3400,2180) R40.1@3400,2231.54 ; RA6.6@3673.94,1728.9 3680,1734.96 3680,1838.66 v1@3685.67,1844.33
  Bottom Layer w10: v1(3200,1495) 3410,1495 3685.67,1770.67 3685.67,1884.33 3400,2170 v1(3400,2180)
  other v1: 3685,1845
LCD_DATA10: R37.2 R48.1 RA6.5 U1.126 | length 1462.6
  Top Layer w10: U1.126@3005,1485 3040,1485 3080,1525 v1(3170,1525) ; R37.2@3330,2133.46 v1(3330,2180) R48.1@3330,2231.54 ; RA6.5@3640.47,1728.9 3640.47,1770.47 v1(3646.3,1776.3)
  Bottom Layer w10: v1(3170,1525) 3395,1525 v1(3646.3,1776.3) 3646.3,1894.52 3395.82,2145 3365,2145 v1(3330,2180)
